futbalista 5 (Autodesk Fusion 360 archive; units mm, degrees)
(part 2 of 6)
sketch "Sketch25" plane through (0, 0, 31.7475) normal (0, 0, 1) x axis (-1, 0, 0)
  line L1 (-17.1956, -65) -> (-17.1956, -78.7443)
  curve K1 (-17.1956, -65) -> (-12.872, -63)
  line L2 (12.872, -63) -> (-12.872, -63)
  curve K2 (12.872, -63) -> (17.1956, -65)
  line L3 (17.1956, -78.7443) -> (17.1956, -65)
  line L4 (41.8394, -62.968) -> (43.3878, -65.6499)
  line L5 (43.3878, -57.718) -> (41.8394, -60.3999)
  line L6 (48.7086, -56.434) -> (45.6119, -56.434)
  line L7 (52.4811, -60.3999) -> (50.9327, -57.718)
  line L8 (75.4516, -15.25) -> (78.5484, -15.25)
  line L9 (71.6792, -11.2841) -> (73.2276, -13.9659)
  line L10 (73.2276, -6.0341) -> (71.6792, -8.7159)
  line L11 (78.5484, -4.75) -> (75.4516, -4.75)
  line L12 (64.8894, 17.6082) -> (76.7924, 24.4804)
  curve K3 (64.8894, 17.6082) -> (60.9956, 20.3525)
  line L13 (48.1236, 42.6475) -> (60.9956, 20.3525)
  curve K4 (48.1236, 42.6475) -> (47.6939, 47.3918)
  line L14 (59.5968, 54.264) -> (47.6939, 47.3918)
  line L15 (33.9041, 62.2984) -> (43.5123, 67.8457)
  line L16 (36.1352, 58.9119) -> (34.5869, 61.5938)
  line L17 (34.5869, 53.6619) -> (36.1352, 56.3438)
  line L18 (29.266, 52.3779) -> (32.3628, 52.3779)
  line L19 (25.4936, 56.3438) -> (27.042, 53.6619)
  line L20 (22.6078, 55.7765) -> (25.2248, 57.2874)
  line L21 (16.2, 55.5086) -> (21.6078, 55.5086)
  line L22 (16.2, 19.4846) -> (16.2, 55.5086)
  line L23 (13.8564, -18.3923) -> (22.8564, -2.8038)
  line L24 (-22.8564, -2.8038) -> (-13.8564, -18.3923)
  line L25 (-16.2, 55.5086) -> (-16.2, 19.4846)
  line L26 (-21.6078, 55.5086) -> (-16.2, 55.5086)
  line L27 (-25.2248, 57.2874) -> (-22.6078, 55.7765)
  line L28 (-27.042, 53.6619) -> (-25.4936, 56.3438)
  line L29 (-32.3628, 52.3779) -> (-29.266, 52.3779)
  line L30 (-36.1352, 56.3438) -> (-34.5869, 53.6619)
  line L31 (-34.5869, 61.5938) -> (-36.1352, 58.9119)
  line L32 (-43.5123, 67.8457) -> (-33.9041, 62.2984)
  line L33 (-47.6939, 47.3918) -> (-59.5968, 54.264)
  curve K5 (-47.6939, 47.3918) -> (-48.1236, 42.6475)
  line L34 (-60.9956, 20.3525) -> (-48.1236, 42.6475)
  curve K6 (-60.9956, 20.3525) -> (-64.8894, 17.6082)
  line L35 (-76.7924, 24.4804) -> (-64.8894, 17.6082)
  line L36 (-75.4516, -4.75) -> (-78.5484, -4.75)
  line L37 (-71.6792, -8.7159) -> (-73.2276, -6.0341)
  line L38 (-73.2276, -13.9659) -> (-71.6792, -11.2841)
  line L39 (-78.5484, -15.25) -> (-75.4516, -15.25)
  line L40 (-50.9327, -57.718) -> (-52.4811, -60.3999)
  line L41 (-45.6119, -56.434) -> (-48.7086, -56.434)
  line L42 (-41.8394, -60.3999) -> (-43.3878, -57.718)
  line L43 (-43.3878, -65.6499) -> (-41.8394, -62.968)
  line L44 (-13.8564, -18.3923) -> (-22.8564, -2.8038)
  line L45 (22.8564, -2.8038) -> (13.8564, -18.3923)
  line L46 (-9, 21.1962) -> (9, 21.1962)
  line L47 (-21.1244, -1.8038) -> (-12.1244, -17.3923)
  line L48 (9, 19.1962) -> (-9, 19.1962)
  line L49 (12.1244, -17.3923) -> (21.1244, -1.8038)
  line L50 (-20.5628, 59.4086) -> (20.5628, 59.4086)
  line L51 (-43.5858, 72.3915) -> (-21.5628, 59.6765)
  line L52 (21.5628, 59.6765) -> (43.5858, 72.3915)
  line L53 (-21.6078, 57.5086) -> (-43.5581, 70.1816)
  line L54 (21.6078, 57.5086) -> (-21.6078, 57.5086)
  line L55 (43.5581, 70.1816) -> (21.6078, 57.5086)
  line L56 (16.2, 55.5086) -> (-16.2, 55.5086)
  arc A1 centre (30.8144, 57.6279) radius 3.7 clockwise from (27.1259, 57.3359) to (27.1259, 57.9198)
  arc A2 centre (30.8144, 57.6279) radius 3.7 clockwise from (28.7173, 54.5795) to (27.1259, 57.3359)
  arc A3 centre (30.8144, 57.6279) radius 3.7 clockwise from (29.223, 54.2876) to (28.7173, 54.5795)
  arc A4 centre (30.8144, 57.6279) radius 3.7 clockwise from (32.4058, 54.2876) to (29.223, 54.2876)
  arc A5 centre (30.8144, 57.6279) radius 3.7 clockwise from (32.9115, 54.5795) to (32.4058, 54.2876)
  arc A6 centre (30.8144, 57.6279) radius 3.7 clockwise from (34.5029, 57.3359) to (32.9115, 54.5795)
  arc A7 centre (30.8144, 57.6279) radius 3.7 clockwise from (34.5029, 57.9198) to (34.5029, 57.3359)
  arc A8 centre (30.8144, 57.6279) radius 3.7 clockwise from (32.9115, 60.6762) to (34.5029, 57.9198)
  arc A9 centre (30.8144, 57.6279) radius 3.7 clockwise from (32.4058, 60.9682) to (32.9115, 60.6762)
  arc A10 centre (30.8144, 57.6279) radius 3.7 clockwise from (31.9266, 61.1568) to (32.4058, 60.9682)
  arc A11 centre (30.8144, 57.6279) radius 3.7 clockwise from (27.2022, 58.4291) to (31.9266, 61.1568)
  arc A12 centre (30.8144, 57.6279) radius 3.7 clockwise from (27.1259, 57.9198) to (27.2022, 58.4291)
  circle C1 centre (30.8144, 57.6279) radius 3.2
  arc A13 centre (-30.8144, 57.6279) radius 3.7 clockwise from (-34.5029, 57.3359) to (-34.5029, 57.9198)
  arc A14 centre (-30.8144, 57.6279) radius 3.7 clockwise from (-32.9115, 54.5795) to (-34.5029, 57.3359)
  arc A15 centre (-30.8144, 57.6279) radius 3.7 clockwise from (-32.4058, 54.2876) to (-32.9115, 54.5795)
  arc A16 centre (-30.8144, 57.6279) radius 3.7 clockwise from (-29.223, 54.2876) to (-32.4058, 54.2876)
  arc A17 centre (-30.8144, 57.6279) radius 3.7 clockwise from (-28.7173, 54.5795) to (-29.223, 54.2876)
  arc A18 centre (-30.8144, 57.6279) radius 3.7 clockwise from (-27.1259, 57.3359) to (-28.7173, 54.5795)
  arc A19 centre (-30.8144, 57.6279) radius 3.7 clockwise from (-27.1259, 57.9198) to (-27.1259, 57.3359)
  arc A20 centre (-30.8144, 57.6279) radius 3.7 clockwise from (-27.2022, 58.4291) to (-27.1259, 57.9198)
  arc A21 centre (-30.8144, 57.6279) radius 3.7 clockwise from (-31.9266, 61.1568) to (-27.2022, 58.4291)
  arc A22 centre (-30.8144, 57.6279) radius 3.7 clockwise from (-32.4058, 60.9682) to (-31.9266, 61.1568)
  arc A23 centre (-30.8144, 57.6279) radius 3.7 clockwise from (-32.9115, 60.6762) to (-32.4058, 60.9682)
  arc A24 centre (-30.8144, 57.6279) radius 3.7 clockwise from (-34.5029, 57.9198) to (-32.9115, 60.6762)
  circle C2 centre (-30.8144, 57.6279) radius 3.2
  arc A25 centre (-77, -10) radius 3.7 clockwise from (-79.6046, -12.6279) to (-80.1895, -8.1246)
  arc A26 centre (-77, -10) radius 3.7 clockwise from (-79.0971, -13.0483) to (-79.6046, -12.6279)
  arc A27 centre (-77, -10) radius 3.7 clockwise from (-78.5914, -13.3403) to (-79.0971, -13.0483)
  arc A28 centre (-77, -10) radius 3.7 clockwise from (-75.4086, -13.3403) to (-78.5914, -13.3403)
  arc A29 centre (-77, -10) radius 3.7 clockwise from (-74.9029, -13.0483) to (-75.4086, -13.3403)
  arc A30 centre (-77, -10) radius 3.7 clockwise from (-73.3115, -10.2919) to (-74.9029, -13.0483)
  arc A31 centre (-77, -10) radius 3.7 clockwise from (-73.3115, -9.7081) to (-73.3115, -10.2919)
  arc A32 centre (-77, -10) radius 3.7 clockwise from (-74.9029, -6.9517) to (-73.3115, -9.7081)
  arc A33 centre (-77, -10) radius 3.7 clockwise from (-75.4086, -6.6597) to (-74.9029, -6.9517)
  arc A34 centre (-77, -10) radius 3.7 clockwise from (-78.5914, -6.6597) to (-75.4086, -6.6597)
  arc A35 centre (-77, -10) radius 3.7 clockwise from (-79.0971, -6.9517) to (-78.5914, -6.6597)
  arc A36 centre (-77, -10) radius 3.7 clockwise from (-80.1895, -8.1246) to (-79.0971, -6.9517)
  circle C3 centre (-77, -10) radius 3.2
  arc A37 centre (-47.1603, -61.684) radius 3.7 clockwise from (-50.8487, -61.9759) to (-50.8487, -61.392)
  arc A38 centre (-47.1603, -61.684) radius 3.7 clockwise from (-50.7384, -62.6257) to (-50.8487, -61.9759)
  arc A39 centre (-47.1603, -61.684) radius 3.7 clockwise from (-47.1308, -65.3838) to (-50.7384, -62.6257)
  arc A40 centre (-47.1603, -61.684) radius 3.7 clockwise from (-45.5689, -65.0242) to (-47.1308, -65.3838)
  arc A41 centre (-47.1603, -61.684) radius 3.7 clockwise from (-45.0632, -64.7323) to (-45.5689, -65.0242)
  arc A42 centre (-47.1603, -61.684) radius 3.7 clockwise from (-43.4718, -61.9759) to (-45.0632, -64.7323)
  arc A43 centre (-47.1603, -61.684) radius 3.7 clockwise from (-43.4718, -61.392) to (-43.4718, -61.9759)
  arc A44 centre (-47.1603, -61.684) radius 3.7 clockwise from (-45.0632, -58.6356) to (-43.4718, -61.392)
  arc A45 centre (-47.1603, -61.684) radius 3.7 clockwise from (-45.5689, -58.3437) to (-45.0632, -58.6356)
  arc A46 centre (-47.1603, -61.684) radius 3.7 clockwise from (-48.7517, -58.3437) to (-45.5689, -58.3437)
  arc A47 centre (-47.1603, -61.684) radius 3.7 clockwise from (-49.2573, -58.6356) to (-48.7517, -58.3437)
  arc A48 centre (-47.1603, -61.684) radius 3.7 clockwise from (-50.8487, -61.392) to (-49.2573, -58.6356)
  circle C4 centre (-47.1603, -61.684) radius 3.2
  arc A49 centre (47.1603, -61.684) radius 3.7 clockwise from (43.4718, -61.9759) to (43.4718, -61.392)
  arc A50 centre (47.1603, -61.684) radius 3.7 clockwise from (45.0632, -64.7323) to (43.4718, -61.9759)
  arc A51 centre (47.1603, -61.684) radius 3.7 clockwise from (45.5689, -65.0242) to (45.0632, -64.7323)
  arc A52 centre (47.1603, -61.684) radius 3.7 clockwise from (47.1308, -65.3838) to (45.5689, -65.0242)
  arc A53 centre (47.1603, -61.684) radius 3.7 clockwise from (50.7384, -62.6257) to (47.1308, -65.3838)
  arc A54 centre (47.1603, -61.684) radius 3.7 clockwise from (50.8487, -61.9759) to (50.7384, -62.6257)
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  point P195 (-16.2, 55.5086)
  point P318 (-16.2, 55.5086)
  point P185 (16.2, 55.5086)
  point P319 (16.2, 55.5086)
  coincident P195 P318
  coincident P185 P319
extrude "Extrude41" new body of existing geometry blind 25
extrude "Extrude39" add sketch "Sketch25" against normal blind 3
circular_pattern "C-Pattern8" TotalAngle 360
combine "Combine20"
extrude "Extrude40" cut sketch "Sketch25" against normal blind 20 and along normal blind 10
extrude "Extrude42" cut sketch "Sketch25" along normal blind 9.003
offset_faces "OffsetFaces11" distance 0.003
sketch "Sketch26" plane through (0, 0, 31.7505) normal (0, 0, 1) x axis (-1, 0, 0)
  line L1 (13.8564, -18.3923) -> (22.8564, -2.8038)
  line L2 (-22.8564, -2.8038) -> (-13.8564, -18.3923)
  line L3 (9, 21.1962) -> (-9, 21.1962)
  line L4 (-21.6078, 55.5086) -> (21.6078, 55.5086)
  line L5 (-27.2022, 58.4291) -> (-22.6078, 55.7765)
  line L6 (-43.5123, 67.8457) -> (-31.9266, 61.1568)
  line L7 (-50.9495, 41.7529) -> (-63.8435, 49.1973)
  curve K1 (-50.9495, 41.7529) -> (-61.6338, 23.2471)
  line L8 (-74.5278, 30.6914) -> (-61.6338, 23.2471)
  line L9 (-10.6844, -65) -> (-10.6844, -79.8887)
  curve K2 (-10.6844, -65) -> (10.6844, -65)
  line L10 (10.6844, -79.8887) -> (10.6844, -65)
  line L11 (61.6338, 23.2471) -> (74.5278, 30.6914)
  curve K3 (61.6338, 23.2471) -> (50.9495, 41.7529)
  line L12 (63.8435, 49.1973) -> (50.9495, 41.7529)
  line L13 (31.9266, 61.1568) -> (43.5123, 67.8457)
  line L14 (22.6078, 55.7765) -> (27.2022, 58.4291)
  circle C1 centre (-47.1603, -61.684) radius 3.2
  circle C2 centre (-77, -10) radius 3.2
  circle C3 centre (47.1603, -61.684) radius 3.2
  arc A1 centre (9, 5.1962) radius 16 clockwise from (9, 21.1962) to (22.8564, -2.8038)
  arc A2 centre (0, -10.3923) radius 16 clockwise from (13.8564, -18.3923) to (-13.8564, -18.3923)
  arc A3 centre (-9, 5.1962) radius 16 clockwise from (-22.8564, -2.8038) to (-9, 21.1962)
  circle C4 centre (-29, -52.2) radius 1.35
  circle C5 centre (29, -3.2) radius 1.35
  circle C6 centre (29, -52.2) radius 1.35
  circle C7 centre (-29, -3.2) radius 1.35
  arc A4 centre (-21.6078, 57.5086) radius 2 clockwise from (-21.6078, 55.5086) to (-22.6078, 55.7765)
  arc A5 centre (-30.8144, 57.6279) radius 3.7 clockwise from (-31.9266, 61.1568) to (-27.2022, 58.4291)
  arc A6 centre (0, 0) radius 80.6 clockwise from (-63.8435, 49.1973) to (-43.5123, 67.8457)
  arc A7 centre (0, 0) radius 80.6 clockwise from (-80.1895, -8.1246) to (-74.5278, 30.6914)
  arc A8 centre (-77, -10) radius 3.7 clockwise from (-79.6046, -12.6279) to (-80.1895, -8.1246)
  arc A9 centre (0, 0) radius 80.6 clockwise from (-50.7384, -62.6257) to (-79.6046, -12.6279)
  arc A10 centre (-47.1603, -61.684) radius 3.7 clockwise from (-47.1308, -65.3838) to (-50.7384, -62.6257)
  arc A11 centre (0, 0) radius 80.6 clockwise from (-10.6844, -79.8887) to (-47.1308, -65.3838)
  arc A12 centre (0, 0) radius 80.6 clockwise from (47.1308, -65.3838) to (10.6844, -79.8887)
  arc A13 centre (47.1603, -61.684) radius 3.7 clockwise from (50.7384, -62.6257) to (47.1308, -65.3838)
  arc A14 centre (0, 0) radius 80.6 clockwise from (79.6046, -12.6279) to (50.7384, -62.6257)
  arc A15 centre (77, -10) radius 3.7 clockwise from (80.1895, -8.1246) to (79.6046, -12.6279)
  arc A16 centre (0, 0) radius 80.6 clockwise from (74.5278, 30.6914) to (80.1895, -8.1246)
  arc A17 centre (0, 0) radius 80.6 clockwise from (43.5123, 67.8457) to (63.8435, 49.1973)
  arc A18 centre (30.8144, 57.6279) radius 3.7 clockwise from (27.2022, 58.4291) to (31.9266, 61.1568)
  arc A19 centre (21.6078, 57.5086) radius 2 clockwise from (22.6078, 55.7765) to (21.6078, 55.5086)
  circle C8 centre (30.8144, 57.6279) radius 3.2
  circle C9 centre (-30.8144, 57.6279) radius 3.2
  circle C10 centre (77, -10) radius 3.2
  circle C11 centre (0, 0) radius 80.6
  point P35 (-10.6844, -79.8887)
  concentric A6 C11
  coincident P35 C11
extrude "Extrude43" cut sketch "Sketch26" profile of L7 K1 L8 L9 K2 L10 L11 K3 L12 C11 along normal blind 59
sketch "Sketch27" plane through (0, 0, 26.75) normal (0, 0, -1) x axis (1, 0, 0)
  line L1 (12.1244, -17.3923) -> (21.1244, -1.8038)
  line L2 (-21.1244, -1.8038) -> (-12.1244, -17.3923)
  line L3 (9, 19.1962) -> (-9, 19.1962)
  line L4 (-29.266, 60.8779) -> (-32.3628, 60.8779)
  line L5 (-27.2256, 57.9119) -> (-28.774, 60.5938)
  line L6 (-28.774, 54.6619) -> (-27.2256, 57.3438)
  line L7 (-32.3628, 54.3779) -> (-29.266, 54.3779)
  line L8 (-34.4032, 57.3438) -> (-32.8548, 54.6619)
  line L9 (-32.8548, 60.5938) -> (-34.4032, 57.9119)
  line L10 (-78.5484, -13.25) -> (-75.4516, -13.25)
  line L11 (-80.5888, -10.2841) -> (-79.0404, -12.9659)
  line L12 (-79.0404, -7.0341) -> (-80.5888, -9.7159)
  line L13 (-75.4516, -6.75) -> (-78.5484, -6.75)
  line L14 (-73.4112, -9.7159) -> (-74.9596, -7.0341)
  line L15 (-74.9596, -12.9659) -> (-73.4112, -10.2841)
  line L16 (50.749, -61.3999) -> (49.2006, -58.718)
  line L17 (49.2006, -64.6499) -> (50.749, -61.968)
  line L18 (45.6119, -64.934) -> (48.7086, -64.934)
  line L19 (43.5715, -61.968) -> (45.1199, -64.6499)
  line L20 (45.1199, -58.718) -> (43.5715, -61.3999)
  line L21 (48.7086, -58.434) -> (45.6119, -58.434)
  line L22 (32.3628, 60.8779) -> (29.266, 60.8779)
  line L23 (34.4032, 57.9119) -> (32.8548, 60.5938)
  line L24 (32.8548, 54.6619) -> (34.4032, 57.3438)
  line L25 (29.266, 54.3779) -> (32.3628, 54.3779)
  line L26 (27.2256, 57.3438) -> (28.774, 54.6619)
  line L27 (28.774, 60.5938) -> (27.2256, 57.9119)
  line L28 (75.4516, -13.25) -> (78.5484, -13.25)
  line L29 (73.4112, -10.2841) -> (74.9596, -12.9659)
  line L30 (74.9596, -7.0341) -> (73.4112, -9.7159)
  line L31 (78.5484, -6.75) -> (75.4516, -6.75)
  line L32 (80.5888, -9.7159) -> (79.0404, -7.0341)
  line L33 (79.0404, -12.9659) -> (80.5888, -10.2841)
  line L34 (-49.2006, -58.718) -> (-50.749, -61.3999)
  line L35 (-45.6119, -58.434) -> (-48.7086, -58.434)
  line L36 (-43.5715, -61.3999) -> (-45.1199, -58.718)
  line L37 (-45.1199, -64.6499) -> (-43.5715, -61.968)
  line L38 (-48.7086, -64.934) -> (-45.6119, -64.934)
  line L39 (-50.749, -61.968) -> (-49.2006, -64.6499)
  line L40 (-21.6078, 57.5086) -> (21.6078, 57.5086)
  line L41 (-42.5123, 69.5778) -> (-21.6078, 57.5086)
  line L42 (-47.9747, 46.9054) -> (-61.7512, 54.8593)
  line L43 (-64.6086, 18.0946) -> (-47.9747, 46.9054)
  line L44 (-78.3852, 26.0485) -> (-64.6086, 18.0946)
  line L45 (-16.6339, -65) -> (-16.6339, -80.9078)
  line L46 (16.6339, -65) -> (-16.6339, -65)
  line L47 (16.6339, -80.9078) -> (16.6339, -65)
  line L48 (64.6086, 18.0946) -> (78.3852, 26.0485)
  line L49 (47.9747, 46.9054) -> (64.6086, 18.0946)
  line L50 (61.7512, 54.8593) -> (47.9747, 46.9054)
  line L51 (21.6078, 57.5086) -> (42.5123, 69.5778)
  line L52 (3, 0) -> (0, 0)
  line L53 (3, -24.0671) -> (3, -5.1962)
  line L54 (-3, -24.0671) -> (-3, -5.1962)
  line L55 (19.3427, 14.6316) -> (3, 5.1962)
  line L56 (22.3427, 9.4355) -> (6, 0)
  line L57 (-22.3427, 9.4355) -> (-6, 0)
  line L58 (-19.3427, 14.6316) -> (-3, 5.1962)
  arc A1 centre (9, 5.1962) radius 14 clockwise from (9, 19.1962) to (21.1244, -1.8038)
  arc A2 centre (0, -10.3923) radius 14 clockwise from (12.1244, -17.3923) to (-12.1244, -17.3923)
  arc A3 centre (-9, 5.1962) radius 14 clockwise from (-21.1244, -1.8038) to (-9, 19.1962)
  arc A4 centre (-30.8144, 57.6279) radius 3.6 clockwise from (-32.8548, 60.5938) to (-32.3628, 60.8779)
  arc A5 centre (-30.8144, 57.6279) radius 3.6 clockwise from (-29.266, 60.8779) to (-28.774, 60.5938)
  arc A6 centre (-30.8144, 57.6279) radius 3.6 clockwise from (-27.2256, 57.9119) to (-27.2256, 57.3438)
  arc A7 centre (-30.8144, 57.6279) radius 3.6 clockwise from (-28.774, 54.6619) to (-29.266, 54.3779)
  arc A8 centre (-30.8144, 57.6279) radius 3.6 clockwise from (-32.3628, 54.3779) to (-32.8548, 54.6619)
  arc A9 centre (-30.8144, 57.6279) radius 3.6 clockwise from (-34.4032, 57.3438) to (-34.4032, 57.9119)
  arc A10 centre (-77, -10) radius 3.6 clockwise from (-74.9596, -12.9659) to (-75.4516, -13.25)
  arc A11 centre (-77, -10) radius 3.6 clockwise from (-78.5484, -13.25) to (-79.0404, -12.9659)
  arc A12 centre (-77, -10) radius 3.6 clockwise from (-80.5888, -10.2841) to (-80.5888, -9.7159)
  arc A13 centre (-77, -10) radius 3.6 clockwise from (-79.0404, -7.0341) to (-78.5484, -6.75)
  arc A14 centre (-77, -10) radius 3.6 clockwise from (-75.4516, -6.75) to (-74.9596, -7.0341)
  arc A15 centre (-77, -10) radius 3.6 clockwise from (-73.4112, -9.7159) to (-73.4112, -10.2841)
  circle C1 centre (-29, -52.2) radius 1.35
  arc A16 centre (47.1603, -61.684) radius 3.6 clockwise from (48.7086, -58.434) to (49.2006, -58.718)
  arc A17 centre (47.1603, -61.684) radius 3.6 clockwise from (50.749, -61.3999) to (50.749, -61.968)
  arc A18 centre (47.1603, -61.684) radius 3.6 clockwise from (49.2006, -64.6499) to (48.7086, -64.934)
  arc A19 centre (47.1603, -61.684) radius 3.6 clockwise from (45.6119, -64.934) to (45.1199, -64.6499)
  arc A20 centre (47.1603, -61.684) radius 3.6 clockwise from (43.5715, -61.968) to (43.5715, -61.3999)
  arc A21 centre (47.1603, -61.684) radius 3.6 clockwise from (45.1199, -58.718) to (45.6119, -58.434)
  circle C2 centre (29, -52.2) radius 1.35
  arc A22 centre (30.8144, 57.6279) radius 3.6 clockwise from (28.774, 60.5938) to (29.266, 60.8779)
  arc A23 centre (30.8144, 57.6279) radius 3.6 clockwise from (32.3628, 60.8779) to (32.8548, 60.5938)
  arc A24 centre (30.8144, 57.6279) radius 3.6 clockwise from (34.4032, 57.9119) to (34.4032, 57.3438)
  arc A25 centre (30.8144, 57.6279) radius 3.6 clockwise from (32.8548, 54.6619) to (32.3628, 54.3779)
  arc A26 centre (30.8144, 57.6279) radius 3.6 clockwise from (29.266, 54.3779) to (28.774, 54.6619)
  arc A27 centre (30.8144, 57.6279) radius 3.6 clockwise from (27.2256, 57.3438) to (27.2256, 57.9119)
  arc A28 centre (77, -10) radius 3.6 clockwise from (79.0404, -12.9659) to (78.5484, -13.25)
  arc A29 centre (77, -10) radius 3.6 clockwise from (75.4516, -13.25) to (74.9596, -12.9659)
  arc A30 centre (77, -10) radius 3.6 clockwise from (73.4112, -10.2841) to (73.4112, -9.7159)
  arc A31 centre (77, -10) radius 3.6 clockwise from (74.9596, -7.0341) to (75.4516, -6.75)
  arc A32 centre (77, -10) radius 3.6 clockwise from (78.5484, -6.75) to (79.0404, -7.0341)
  arc A33 centre (77, -10) radius 3.6 clockwise from (80.5888, -9.7159) to (80.5888, -10.2841)
  circle C3 centre (-29, -3.2) radius 1.35
  circle C4 centre (29, -3.2) radius 1.35
  arc A34 centre (-47.1603, -61.684) radius 3.6 clockwise from (-50.749, -61.968) to (-50.749, -61.3999)
  arc A35 centre (-47.1603, -61.684) radius 3.6 clockwise from (-49.2006, -58.718) to (-48.7086, -58.434)
  arc A36 centre (-47.1603, -61.684) radius 3.6 clockwise from (-45.6119, -58.434) to (-45.1199, -58.718)
  arc A37 centre (-47.1603, -61.684) radius 3.6 clockwise from (-43.5715, -61.3999) to (-43.5715, -61.968)
  arc A38 centre (-47.1603, -61.684) radius 3.6 clockwise from (-45.1199, -64.6499) to (-45.6119, -64.934)
  arc A39 centre (-47.1603, -61.684) radius 3.6 clockwise from (-48.7086, -64.934) to (-49.2006, -64.6499)
  arc A40 centre (-43.5123, 67.8457) radius 2 clockwise from (-44.592, 69.5292) to (-42.5123, 69.5778)
  arc A41 centre (0, 0) radius 82.6 clockwise from (-61.7512, 54.8593) to (-44.592, 69.5292)
  arc A42 centre (0, 0) radius 82.6 clockwise from (-16.6339, -80.9078) to (-78.3852, 26.0485)
  arc A43 centre (0, 0) radius 82.6 clockwise from (78.3852, 26.0485) to (16.6339, -80.9078)
  arc A44 centre (0, 0) radius 82.6 clockwise from (44.592, 69.5292) to (61.7512, 54.8593)
  arc A45 centre (43.5123, 67.8457) radius 2 clockwise from (42.5123, 69.5778) to (44.592, 69.5292)
  arc A46 centre (9, -5.1962) radius 6 clockwise from (3, -5.1962) to (6, 0)
  arc A47 centre (-9, -5.1962) radius 6 clockwise from (-6, 0) to (-3, -5.1962)
  arc A48 centre (0, 10.3923) radius 6 clockwise from (3, 5.1962) to (-3, 5.1962)
  point P1 (0, 0)
  point P114 (0, 0)
  point P116 (3, -24.0671)
  point P117 (-3, -24.0671)
  point P115 (3, 0)
  coincident P1 P114
  coincident A2 P116
  perpendicular L52 L53
  coincident A2 P117
  perpendicular L52 L54
  coincident P115 L53
  tangent L56 A46
  tangent L53 A46
  tangent L54 A47
  tangent L57 A47
  equal A46 A47
  tangent L58 A48
  tangent L55 A48
  equal A46 A48
  dimension "d232" radius A46 = 6
extrude "Extrude44" add sketch "Sketch27" profile of A1 A2 A3 L53 L54 L55 L56 L57 L58 A46 A47 A48 against normal blind 3
position "Position24"
sketch "Sketch28" plane through (0, 0, 31.7505) normal (0, 0, 1) x axis (-1, 0, 0)
  line L1 (13.8564, -18.3923) -> (22.8564, -2.8038)
  line L2 (-22.8564, -2.8038) -> (-13.8564, -18.3923)
  line L3 (9, 21.1962) -> (-9, 21.1962)
  line L4 (-21.6078, 55.5086) -> (21.6078, 55.5086)
  line L5 (-27.2022, 58.4291) -> (-22.6078, 55.7765)
  line L6 (-43.5123, 67.8457) -> (-31.9266, 61.1568)
  line L7 (31.9266, 61.1568) -> (43.5123, 67.8457)
  line L8 (22.6078, 55.7765) -> (27.2022, 58.4291)
  line L9 (-14, 32.5) -> (-14, 39.5)
  line L10 (14, 32.5) -> (-14, 32.5)
  line L11 (14, 39.5) -> (14, 32.5)
  line L12 (-14, 39.5) -> (14, 39.5)
  line L13 (14, 20.3948) -> (14, 32.5)
  line L14 (-14, 20.3948) -> (-14, 32.5)
  line L15 (-20.5628, 59.4086) -> (20.5628, 59.4086)
  line L16 (-43.5858, 72.3915) -> (-21.5628, 59.6765)
  line L17 (21.5628, 59.6765) -> (43.5858, 72.3915)
  line L18 (-21.6078, 57.5086) -> (-43.5581, 70.1816)
  line L19 (21.6078, 57.5086) -> (-21.6078, 57.5086)
  line L20 (43.5581, 70.1816) -> (21.6078, 57.5086)
  line L21 (-14, 57.5086) -> (-14, 39.5)
  line L22 (14, 57.5086) -> (14, 39.5)
  line L23 (-21.6078, 57.5086) -> (-21.6078, 39.5)
  line L24 (-21.6078, 15.0472) -> (-21.6078, 39.5)
  line L25 (21.6078, 15.0472) -> (21.6078, 39.5)
  line L26 (21.6078, 57.5086) -> (21.6078, 39.5)
  line L27 (25, 5.1961) -> (-25, 5.1962)
  line L28 (25, 59.4671) -> (25, 5.1961)
  line L29 (-25, 59.4671) -> (-25, 5.1962)
  line L30 (-2, 53.9086) -> (-2, 22.7962)
  line L31 (-5.2, 22.7962) -> (-5.2, 53.9086)
  line L32 (-3.6, 55.5086) -> (-3.6, 21.1962)
  line L33 (5.2, 53.9086) -> (5.2, 22.7962)
  line L34 (2, 22.7962) -> (2, 53.9086)
  line L35 (3.6, 55.5086) -> (3.6, 21.1962)
  line L36 (21.6078, 21.1962) -> (0, 21.1962)
  line L37 (-21.6078, 21.1962) -> (0, 21.1962)
  line L38 (25, 61.661) -> (25, 59.4671)
  line L39 (-25, 61.661) -> (-25, 59.4671)
  circle C1 centre (-47.1603, -61.684) radius 3.2
  circle C2 centre (-77, -10) radius 3.2
  circle C3 centre (47.1603, -61.684) radius 3.2
  arc A1 centre (9, 5.1962) radius 16 clockwise from (9, 21.1962) to (22.8564, -2.8038)
  arc A2 centre (0, -10.3923) radius 16 clockwise from (13.8564, -18.3923) to (-13.8564, -18.3923)
  arc A3 centre (-9, 5.1962) radius 16 clockwise from (-22.8564, -2.8038) to (-9, 21.1962)
  circle C4 centre (-29, -52.2) radius 1.35
  circle C5 centre (29, -3.2) radius 1.35
  circle C6 centre (29, -52.2) radius 1.35
  circle C7 centre (-29, -3.2) radius 1.35
  arc A4 centre (-21.6078, 57.5086) radius 2 clockwise from (-21.6078, 55.5086) to (-22.6078, 55.7765)
  arc A5 centre (-30.8144, 57.6279) radius 3.7 clockwise from (-31.9266, 61.1568) to (-27.2022, 58.4291)
  arc A6 centre (0, 0) radius 80.6 clockwise from (-80.1895, -8.1246) to (-43.5123, 67.8457)
  arc A7 centre (-77, -10) radius 3.7 clockwise from (-79.6046, -12.6279) to (-80.1895, -8.1246)
  arc A8 centre (0, 0) radius 80.6 clockwise from (-50.7384, -62.6257) to (-79.6046, -12.6279)
  arc A9 centre (-47.1603, -61.684) radius 3.7 clockwise from (-47.1308, -65.3838) to (-50.7384, -62.6257)
  arc A10 centre (0, 0) radius 80.6 clockwise from (47.1308, -65.3838) to (-47.1308, -65.3838)
  arc A11 centre (47.1603, -61.684) radius 3.7 clockwise from (50.7384, -62.6257) to (47.1308, -65.3838)
  arc A12 centre (0, 0) radius 80.6 clockwise from (79.6046, -12.6279) to (50.7384, -62.6257)
  arc A13 centre (77, -10) radius 3.7 clockwise from (80.1895, -8.1246) to (79.6046, -12.6279)
  arc A14 centre (0, 0) radius 80.6 clockwise from (43.5123, 67.8457) to (80.1895, -8.1246)
  arc A15 centre (30.8144, 57.6279) radius 3.7 clockwise from (27.2022, 58.4291) to (31.9266, 61.1568)
  arc A16 centre (21.6078, 57.5086) radius 2 clockwise from (22.6078, 55.7765) to (21.6078, 55.5086)
  circle C8 centre (30.8144, 57.6279) radius 3.2
  circle C9 centre (-30.8144, 57.6279) radius 3.2
  circle C10 centre (77, -10) radius 3.2
  circle C11 centre (3.6, 36) radius 1.6
  circle C12 centre (-3.6, 36) radius 1.6
  arc A17 centre (-20.5628, 61.4086) radius 2 clockwise from (-20.5628, 59.4086) to (-21.5628, 59.6765)
  arc A18 centre (0, 0) radius 84.5 clockwise from (43.5858, 72.3915) to (-43.5858, 72.3915)
  arc A19 centre (20.5628, 61.4086) radius 2 clockwise from (21.5628, 59.6765) to (20.5628, 59.4086)
  arc A20 centre (0, 0) radius 82.6 clockwise from (43.5581, 70.1816) to (-43.5581, 70.1816)
  arc A21 centre (-3.6, 53.9086) radius 1.6 clockwise from (-5.2, 53.9086) to (-2, 53.9086)
  arc A22 centre (-3.6, 22.7962) radius 1.6 clockwise from (-2, 22.7962) to (-5.2, 22.7962)
  arc A23 centre (3.6, 53.9086) radius 1.6 clockwise from (2, 53.9086) to (5.2, 53.9086)
  arc A24 centre (3.6, 22.7962) radius 1.6 clockwise from (5.2, 22.7962) to (2, 22.7962)
  point P46 (14, 32.5)
  point P48 (14, 32.5)
  point P49 (14, 20.3948)
  point P45 (-14, 32.5)
  point P50 (-14, 32.5)
  point P51 (-14, 20.3948)
  point P44 (-14, 39.5)
  point P65 (-14, 39.5)
  point P66 (-14, 57.5086)
  point P47 (14, 39.5)
  point P67 (14, 39.5)
  point P63 (-21.6078, 57.5086)
  point P70 (-21.6078, 57.5086)
  point P71 (-21.6078, 15.0472)
  point P75 (-25, 5.1962)
  point P76 (25, 5.1961)
  point P77 (25, 59.4671)
  point P78 (-25, 59.4671)
  point P85 (-3.6, 21.1962)
  point P86 (-3.6, 55.5086)
  point P93 (3.6, 21.1962)
  point P94 (3.6, 55.5086)
  point P95 (0, 21.1962)
  point P96 (21.6078, 21.1962)
  point P97 (-21.6078, 21.1962)
  point P98 (25, 61.661)
  point P99 (-25, 61.661)
  coincident P46 P48
  coincident A1 P49
  perpendicular L10 L13
  coincident P45 P50
  coincident A3 P51
  perpendicular L10 L14
  coincident P44 P65
  coincident L19 P66
  perpendicular L19 L21
  coincident P47 P67
  perpendicular L4 L22
  coincident P63 P70
  perpendicular L19 L23
  coincident A3 P71
  coincident A3 P75
  coincident A1 P76
  coincident L20 P77
  perpendicular L27 L28
  coincident L18 P78
  perpendicular L27 L29
  tangent L30 A21
  tangent A21 L31
  parallel L30 L31
  tangent L31 A22
  tangent L30 A22
  midpoint A22 P85
  midpoint A21 P86
  perpendicular L4 L32
  coincident L3 P85
  tangent L33 A23
  tangent A23 L34
  parallel L33 L34
  tangent L34 A24
  tangent L33 A24
  midpoint A24 P93
  midpoint A23 P94
  coincident L4 P94
  perpendicular L4 L35
  coincident L3 P93
  midpoint L3 P95
  coincident L25 P96
  perpendicular L25 L36
  coincident L24 P97
  perpendicular L24 L37
  coincident L17 P98
  parallel L28 L38
  coincident L16 P99
  parallel L29 L39
extrude "Extrude45" add sketch "Sketch28" profile of A1 A3 L4 A4 L5 L8 A16 L13 L14 L15 A17 L16 L17 A19 L18 L19 L20 L21 L22 L23 L24 L25 L26 L28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 along normal blind 8
extrude "Extrude46" cut sketch "Sketch28" profile of L3 L4 C11 C12 L9 L10 L11 L12 L13 L14 L21 L22 L23 L24 L25 L26 L30 A21 L31 A22 L33 A23 L34 A24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 against normal blind 5.0005
extrude "Extrude47" add sketch "Sketch28" profile of A1 A3 L3 L4 A4 L5 L8 A16 L9 L10 L11 L12 L13 L14 L15 A17 L16 L17 A19 L18 L19 L20 L21 L22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 along normal blind 8.9995 and along normal blind 8
extrude "Extrude48" add of existing geometry blind 26.5 second side blind -20
extrude "Extrude49" cut of existing geometry blind -4
extrude "Extrude50" add of existing geometry blind 1.5
extrude "Extrude51" cut of existing geometry blind -2.9995
sketch "Sketch30" plane through (0, 0, -23.25) normal (0, 0, 1) x axis (-1, 0, 0)
  line L1 (11.2, 24.5) -> (-11.2, 24.5)
  line L2 (11.2, 61.4086) -> (11.2, 24.5)
  line L3 (-11.2, 61.4086) -> (11.2, 61.4086)
  line L4 (-11.2, 24.5) -> (-11.2, 61.4086)
  line L5 (21.0719, 59.5086) -> (-21.0719, 59.5086)
  line L6 (11.2, 59.5086) -> (21.0719, 59.5086)
  line L7 (-11.2, 59.5086) -> (11.2, 59.5086)
  line L8 (-21.0719, 59.5086) -> (-11.2, 59.5086)
  line L9 (14.2, 59.5086) -> (-14.2, 59.5086)
  line L10 (-14.2, 59.5086) -> (14.2, 59.5086)
  line L11 (-21.0719, 59.5086) -> (-42.5581, 71.9136)
  line L12 (-42.5581, 71.9136) -> (-21.0719, 59.5086)
  line L13 (21.0719, 59.5086) -> (42.5581, 71.9136)
  line L14 (42.5581, 71.9136) -> (21.0719, 59.5086)
  line L15 (30.8285, 65.6035) -> (21.4288, 60.1765)
  line L16 (30.0785, 66.9025) -> (30.8285, 65.6035)
  line L17 (20.5628, 61.4086) -> (30.0785, 66.9025)
  line L18 (11.2, 61.4086) -> (20.5628, 61.4086)
  line L19 (11.2, 59.9086) -> (11.2, 61.4086)
  line L20 (20.4288, 59.9086) -> (11.2, 59.9086)
  line L21 (-11.2, 59.9086) -> (-20.4288, 59.9086)
  line L22 (-11.2, 61.4086) -> (-11.2, 59.9086)
  line L23 (-20.5628, 61.4086) -> (-11.2, 61.4086)
  line L24 (-30.0785, 66.9025) -> (-20.5628, 61.4086)
  line L25 (-30.8285, 65.6035) -> (-30.0785, 66.9025)
  line L26 (-21.4288, 60.1765) -> (-30.8285, 65.6035)
  line L27 (-31.0285, 65.257) -> (-30.8285, 65.6035)
  line L28 (31.0285, 65.257) -> (30.8285, 65.6035)
  line L29 (-11.2, 59.9086) -> (11.2, 59.9086)
  circle C1 centre (-6, 30.7) radius 1.7
  circle C2 centre (6, 44.2) radius 1.7
  arc A1 centre (20.4288, 61.9086) radius 2 clockwise from (21.4288, 60.1765) to (20.4288, 59.9086)
  arc A2 centre (-20.4288, 61.9086) radius 2 clockwise from (-20.4288, 59.9086) to (-21.4288, 60.1765)
  point P33 (-30.8285, 65.6035)
  point P34 (-30.8285, 65.6035)
  point P35 (-31.0285, 65.257)
  point P21 (30.8285, 65.6035)
  point P36 (30.8285, 65.6035)
  point P37 (31.0285, 65.257)
  point P25 (11.2, 59.9086)
  point P38 (11.2, 59.9086)
  point P29 (-11.2, 59.9086)
  point P39 (-11.2, 59.9086)
  coincident P33 P34
  coincident L12 P35
  perpendicular L12 L27
  coincident P21 P36
  coincident L13 P37
  perpendicular L13 L28
  coincident P25 P38
  coincident P29 P39
extrude "Extrude55" new body sketch "Sketch30" profile of L2 L3 L4 L5 L6 L7 L8 L9 L10 L11 L12 L13 L14 A1 L15 L16 L17 L18 L19 L20 A2 L21 L22 L23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 along normal blind 27.5 and along normal blind 7
extrude "Extrude56" new body of existing geometry blind 2.6
extrude "Extrude57" add of existing geometry blind 0.309
offset_faces "OffsetFaces12" distance -0.2
draft "Draft1" Angle1 45 Angle2 0
draft "Draft2" Angle1 45 Angle2 0
sketch "Sketch31" plane through (0, 0, 0) normal (0, 1, 0) x axis (1, 0, 0)
  line L1 (-73.8, -31.7505) -> (-80.2, -31.7505)
  line L2 (34.0144, -31.7505) -> (27.6144, -31.7505)
  line L3 (-27.6144, -31.7505) -> (-34.0144, -31.7505)
  line L4 (27.65, -31.7505) -> (30.35, -31.7505)
  line L5 (-30.35, -31.7505) -> (-27.65, -31.7505)
  line L6 (-30.35, -31.7505) -> (-27.65, -31.7505)
  line L7 (27.65, -31.7505) -> (30.35, -31.7505)
  line L8 (-43.9603, -31.7505) -> (-50.3603, -31.7505)
  line L9 (80.2, -31.7505) -> (73.8, -31.7505)
  line L10 (50.3603, -31.7505) -> (43.9603, -31.7505)
  line L11 (27.2022, -31.7505) -> (25, -31.7505)
  line L12 (27.2022, -31.7505) -> (31.9266, -31.7505)
  line L13 (43.5123, -31.7505) -> (31.9266, -31.7505)
  line L14 (43.5123, -31.7505) -> (80.6, -31.7505)
  line L15 (79.6046, -31.7505) -> (80.7, -31.7505)
  line L16 (50.7384, -31.7505) -> (79.6046, -31.7505)
  line L17 (47.1308, -31.7505) -> (50.7384, -31.7505)
  line L18 (-47.1308, -31.7505) -> (47.1308, -31.7505)
  line L19 (-50.7384, -31.7505) -> (-47.1308, -31.7505)
  line L20 (-79.6046, -31.7505) -> (-50.7384, -31.7505)
  line L21 (-80.7, -31.7505) -> (-79.6046, -31.7505)
  line L22 (-43.5123, -31.7505) -> (-80.6, -31.7505)
  line L23 (-31.9266, -31.7505) -> (-43.5123, -31.7505)
  line L24 (-31.9266, -31.7505) -> (-27.2022, -31.7505)
  line L25 (-25, -31.7505) -> (-27.2022, -31.7505)
  line L26 (-22.8564, -31.7505) -> (-25, -31.7505)
  line L27 (-13.8564, -31.7505) -> (-22.8564, -31.7505)
  line L28 (13.8564, -31.7505) -> (-13.8564, -31.7505)
  line L29 (22.8564, -31.7505) -> (13.8564, -31.7505)
  line L30 (25, -31.7505) -> (22.8564, -31.7505)
  line L31 (-6, -26.75) -> (-22.3427, -26.75)
  line L32 (-6, -26.75) -> (-3, -26.75)
  line L33 (3, -26.75) -> (6, -26.75)
  line L34 (22.3427, -26.75) -> (6, -26.75)
  line L35 (3, -26.75) -> (19.3427, -26.75)
  line L36 (-3, -26.75) -> (3, -26.75)
  line L37 (-19.3427, -26.75) -> (-3, -26.75)
  line L38 (-49.2006, -26.75) -> (-50.7603, -26.75)
  line L39 (-50, -31.7505) -> (-50, -26.75)
  line L40 (-44.592, -34.75) -> (-44.592, -26.75)
  line L41 (82.6, -34.75) -> (-82.6, -34.75)
  line L42 (44.592, -26.75) -> (44.592, -34.75)
  line L43 (61.7512, -26.75) -> (44.592, -26.75)
  curve K1 (78.3852, -26.75) -> (61.7512, -26.75)
  line L44 (82.6, -26.75) -> (16.6339, -26.75)
  curve K2 (-16.6339, -26.75) -> (16.6339, -26.75)
  line L45 (-16.6339, -26.75) -> (-82.6, -26.75)
  curve K3 (-61.7512, -26.75) -> (-78.3852, -26.75)
  line L46 (-44.592, -26.75) -> (-61.7512, -26.75)
  line L47 (21.6078, -26.75) -> (-21.6078, -26.75)
  line L48 (-21.6078, -26.75) -> (21.6078, -26.75)
  line L49 (-12.1244, -26.75) -> (-3, -26.75)
  line L50 (-21.1244, -26.75) -> (-12.1244, -26.75)
  line L51 (-23, -26.75) -> (-21.1244, -26.75)
  line L52 (21.1244, -26.75) -> (23, -26.75)
  line L53 (12.1244, -26.75) -> (21.1244, -26.75)
  line L54 (3, -26.75) -> (12.1244, -26.75)
  line L55 (-19.3427, -26.75) -> (-9, -26.75)
  line L56 (9, -26.75) -> (-9, -26.75)
  line L57 (9, -26.75) -> (19.3427, -26.75)
  line L58 (-32.8548, -26.75) -> (-32.3628, -26.75)
  line L59 (-29.266, -26.75) -> (-32.3628, -26.75)
  line L60 (-29.266, -26.75) -> (-28.774, -26.75)
  line L61 (-27.2256, -26.75) -> (-28.774, -26.75)
  line L62 (-27.2256, -26.75) -> (-27.2144, -26.75)
  line L63 (-28.774, -26.75) -> (-27.2256, -26.75)
  line L64 (-29.266, -26.75) -> (-28.774, -26.75)
  line L65 (-32.3628, -26.75) -> (-29.266, -26.75)
  line L66 (-32.8548, -26.75) -> (-32.3628, -26.75)
  line L67 (-34.4032, -26.75) -> (-32.8548, -26.75)
  line L68 (-34.4144, -26.75) -> (-34.4032, -26.75)
  line L69 (-32.8548, -26.75) -> (-34.4032, -26.75)
  line L70 (-75.4516, -26.75) -> (-74.9596, -26.75)
  line L71 (-78.5484, -26.75) -> (-75.4516, -26.75)
  line L72 (-79.0404, -26.75) -> (-78.5484, -26.75)
  line L73 (-80.5888, -26.75) -> (-79.0404, -26.75)
  line L74 (-80.6, -26.75) -> (-80.5888, -26.75)
  line L75 (-79.0404, -26.75) -> (-80.5888, -26.75)
  line L76 (-79.0404, -26.75) -> (-78.5484, -26.75)
  line L77 (-75.4516, -26.75) -> (-78.5484, -26.75)
  line L78 (-75.4516, -26.75) -> (-74.9596, -26.75)
  line L79 (-73.4112, -26.75) -> (-74.9596, -26.75)
  line L80 (-73.4112, -26.75) -> (-73.4, -26.75)
  line L81 (-74.9596, -26.75) -> (-73.4112, -26.75)
  line L82 (-30.35, -26.75) -> (-27.65, -26.75)
  line L83 (48.7086, -26.75) -> (49.2006, -26.75)
  line L84 (50.749, -26.75) -> (49.2006, -26.75)
  line L85 (50.749, -26.75) -> (50.7603, -26.75)
  line L86 (49.2006, -26.75) -> (50.749, -26.75)
  line L87 (48.7086, -26.75) -> (49.2006, -26.75)
  line L88 (45.6119, -26.75) -> (48.7086, -26.75)
  line L89 (45.1199, -26.75) -> (45.6119, -26.75)
  line L90 (43.5715, -26.75) -> (45.1199, -26.75)
  line L91 (43.5603, -26.75) -> (43.5715, -26.75)
  line L92 (45.1199, -26.75) -> (43.5715, -26.75)
  line L93 (45.1199, -26.75) -> (45.6119, -26.75)
  line L94 (48.7086, -26.75) -> (45.6119, -26.75)
  line L95 (27.65, -26.75) -> (30.35, -26.75)
  line L96 (28.774, -26.75) -> (29.266, -26.75)
  line L97 (32.3628, -26.75) -> (29.266, -26.75)
  line L98 (32.3628, -26.75) -> (32.8548, -26.75)
  line L99 (34.4032, -26.75) -> (32.8548, -26.75)
  line L100 (34.4032, -26.75) -> (34.4144, -26.75)
  line L101 (32.8548, -26.75) -> (34.4032, -26.75)
  line L102 (32.3628, -26.75) -> (32.8548, -26.75)
  line L103 (29.266, -26.75) -> (32.3628, -26.75)
  line L104 (28.774, -26.75) -> (29.266, -26.75)
  line L105 (27.2256, -26.75) -> (28.774, -26.75)
  line L106 (27.2144, -26.75) -> (27.2256, -26.75)
  line L107 (28.774, -26.75) -> (27.2256, -26.75)
  line L108 (78.5484, -26.75) -> (79.0404, -26.75)
  line L109 (75.4516, -26.75) -> (78.5484, -26.75)
  line L110 (74.9596, -26.75) -> (75.4516, -26.75)
  line L111 (73.4112, -26.75) -> (74.9596, -26.75)
  line L112 (73.4, -26.75) -> (73.4112, -26.75)
  line L113 (74.9596, -26.75) -> (73.4112, -26.75)
  line L114 (74.9596, -26.75) -> (75.4516, -26.75)
  line L115 (78.5484, -26.75) -> (75.4516, -26.75)
  line L116 (78.5484, -26.75) -> (79.0404, -26.75)
  line L117 (80.5888, -26.75) -> (79.0404, -26.75)
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  point P48 (-50, -31.7505)
  point P51 (-50, -26.75)
  point P52 (-50, -29.2502)
  coincident L22 P48
  coincident L38 P51
  perpendicular L8 L39
  midpoint L39 P52
  dimension "d273" diameter = 7
extrude "Extrude58" cut sketch "Sketch31" distance 20
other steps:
derived_base_feature "Derived Base Feature1"
derived_base_feature "Derived Base Feature1"
base_feature "Base Feature"
create_component "CreateComponent1"
create_component "CreateComponent2"
cylinder_primitive "CylinderPrimitive1" Height -7 Diameter 173
cylinder_primitive "CylinderPrimitive1" Height -7 Diameter 173

design "Solenoid JF-0826B"
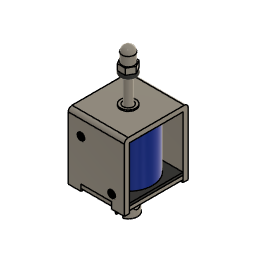
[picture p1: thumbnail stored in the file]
description: STEP AP214
part number: Solenoid JF-0826B

design "18650 battery variations" references "Battery 18650"
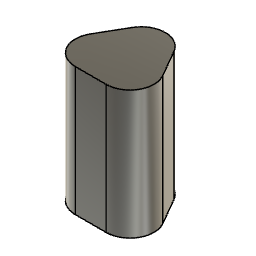
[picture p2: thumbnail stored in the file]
sketch "Sketch1" plane through (0, 0, 0) normal (0, 0, 1) x axis (1, 0, 0)
  line L1 (-16.7942, -0.6962) -> (-7.7942, 14.8923)
  line L2 (9, -14.1962) -> (-9, -14.1962)
  line L3 (7.7942, 14.8923) -> (16.7942, -0.6962)
  circle C1 centre (-9, -5.1962) radius 9
  circle C2 centre (9, -5.1962) radius 9
  circle C3 centre (0, 10.3923) radius 9
  point P4 (-16.7942, -0.6962)
  coincident C1 P4
  tangent C1 L1
  dimension "d6" diameter C1 = 18
  dimension "d11" C-Pattern1-Angle = 360
extrude "Extrude1" new body sketch "Sketch1" along normal blind 65
copy_paste_bodies "CopyPasteBodies2"
offset_faces "OffsetFaces1" distance 5
component_insert "Component Insert"
position "Position4"
step "00000000-0000-0000-0000-000000000000" TotalAngle 360
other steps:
base_feature "Base Feature"

design "25d-metal-gearmotor-20.4"
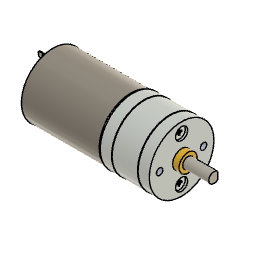
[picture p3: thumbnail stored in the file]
description: STEP AP214
part number: 25d-metal-gearmotor-20.4

design "25d-metal-gearmotor-34-47"
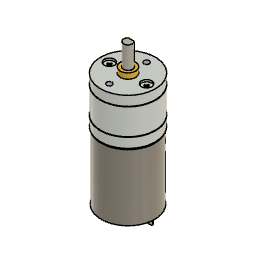
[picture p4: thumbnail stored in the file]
description: STEP AP214
part number: 25d-metal-gearmotor-34-47

design "light sensor"
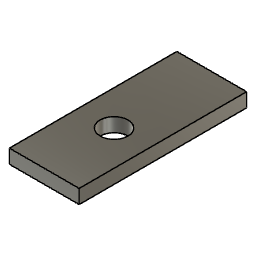
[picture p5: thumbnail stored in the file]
sketch "Sketch1" plane through (0, 0, 0) normal (0, 0, 1) x axis (1, 0, 0)
  line L1 (2.5, -6) -> (2.5, 6)
  line L2 (-2.5, -6) -> (2.5, -6)
  line L3 (-2.5, 6) -> (-2.5, -6)
  line L4 (2.5, 6) -> (-2.5, 6)
  circle C1 centre (0, -1) radius 1
  perpendicular L1 L2
  perpendicular L1 L4
canvas "Canvas1" sketch "Sketch1"
extrude "Extrude1" new body sketch "Sketch1" against normal blind 1

design "cam v2.1 rpi"
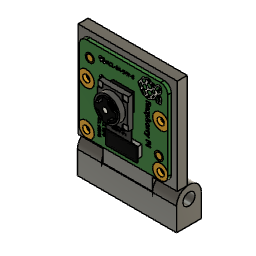
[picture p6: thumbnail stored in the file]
base_feature "Base Feature2"
position "Position1"
base_feature "Base Feature1"
position "Position2"
position "Position3"
position "Position4"
position "Position5"
position "Position6"
position "Position7"
position "Position8"
copy_paste_bodies "CutPasteBodies"
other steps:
base_feature "Base Feature1" bodies "camera mount", "2nd floor"
create_component "CreateComponent1"
named bodies: "camera mount", "2nd floor"

design "omniwheel"
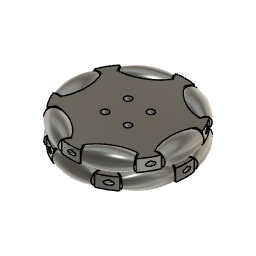
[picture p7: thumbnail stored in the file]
sketch "Sketch1" plane through (0, 0, 0) normal (0, 0, 1) x axis (1, 0, 0)
  line L1 (20.3961, 22) -> (-20.3961, 22)
  line L2 (0, 14) -> (0, 30)
  line L3 (15, 18.0192) -> (15, 25.9808)
  line L4 (-15, 18.0192) -> (-15, 25.9808)
  line L5 (-8.1051, -22) -> (-15, -25.9808)
  line L6 (-29.2506, 6.6635) -> (-8.8545, -28.6635)
  line L7 (-12.1244, -7) -> (-25.9808, -15)
  line L8 (-23.1051, 3.9808) -> (-30, 0)
  line L9 (23.1051, 3.9808) -> (30, 0)
  line L10 (8.8545, -28.6635) -> (29.2506, 6.6635)
  line L11 (12.1244, -7) -> (25.9808, -15)
  line L12 (8.1051, -22) -> (15, -25.9808)
  circle C1 centre (0, 0) radius 30
  arc A1 centre (0, 44) radius 30 clockwise from (20.3961, 22) to (-20.3961, 22)
  arc A2 centre (-38.1051, -22) radius 30 clockwise from (-29.2506, 6.6635) to (-8.8545, -28.6635)
  arc A3 centre (38.1051, -22) radius 30 clockwise from (8.8545, -28.6635) to (29.2506, 6.6635)
  point P1 (0, 0)
  point P2 (0, 0)
  point P6 (0, 30)
  point P7 (0, 14)
  point P8 (15, 25.9808)
  point P9 (15, 18.0192)
  coincident P1 P2
  horizontal L1
  coincident C1 P6
  midpoint A1 P7
  vertical L2
  coincident C1 P8
  coincident A1 P9
  perpendicular L1 L3
  dimension "d8" C-Pattern1-Angle = 360
extrude "Extrude1" new body sketch "Sketch1" distance 3 bodies "koliesko1"
revolve "Revolve1" sketch "Sketch1" AlongAngle 360
circular_pattern "C-Pattern1" TotalAngle 360
sketch "Sketch2" plane through (-7.5, 12.9904, 0) normal (0.5, -0.866, 0) x axis (0.866, 0.5, 0)
  line L1 (-25.9808, -3) -> (-25.9808, 3)
  line L2 (-19.3834, -3) -> (-25.9808, -3)
  line L3 (-25.9808, 3) -> (-19.3834, 3)
  arc A1 centre (-22, 0) radius 3.9808 clockwise from (-19.3834, 3) to (-19.3834, -3)
  circle C1 centre (-22, 0) radius 1.5
  circle C2 centre (-22, 0) radius 3.9808
  concentric A1 C1
  concentric C1 C2
revolve "Revolve2" sketch "Sketch1" AlongAngle 360 bodies "valcek"
extrude "Extrude2" cut sketch "Sketch2" profile of C1 against normal blind 2.5 and along normal blind 32.5
offset_faces "OffsetFaces6" distance -0.2
circular_pattern "C-Pattern2" TotalAngle 360
offset_faces "OffsetFaces1" distance -0.2
circular_pattern "C-Pattern3" TotalAngle 360
sketch "Sketch3" plane through (0, 0, 3) normal (0, 0, 1) x axis (-1, 0, 0)
  line L1 (14.7991, 26.0957) -> (9.0374, 22.7692)
  line L2 (-9.0374, 22.7692) -> (-14.7991, 26.0957)
  curve K1 (-24.2374, -3.558) -> (-9.0374, 22.7692)
  line L3 (-29.9991, -0.2315) -> (-24.2374, -3.558)
  line L4 (-15.2, -19.2113) -> (-15.2, -25.8643)
  curve K2 (15.2, -19.2113) -> (-15.2, -19.2113)
  line L5 (15.2, -25.8643) -> (15.2, -19.2113)
  line L6 (24.2374, -3.558) -> (29.9991, -0.2315)
  curve K3 (9.0374, 22.7692) -> (24.2374, -3.558)
  curve K4 (-15.2, 19.2113) -> (15.2, 19.2113)
  line L7 (-15.2, 25.8643) -> (-15.2, 19.2113)
  line L8 (-24.2374, 3.558) -> (-29.9991, 0.2315)
  curve K5 (-9.0374, -22.7692) -> (-24.2374, 3.558)
  line L9 (-14.7991, -26.0957) -> (-9.0374, -22.7692)
  line L10 (9.0374, -22.7692) -> (14.7991, -26.0957)
  curve K6 (24.2374, 3.558) -> (9.0374, -22.7692)
  line L11 (29.9991, 0.2315) -> (24.2374, 3.558)
  line L12 (15.2, 19.2113) -> (15.2, 25.8643)
  arc A1 centre (0, 0) radius 30 clockwise from (-14.7991, 26.0957) to (14.7991, 26.0957)
  arc A2 centre (0, 0) radius 30 clockwise from (-15.2, -25.8643) to (-29.9991, -0.2315)
  arc A3 centre (0, 0) radius 30 clockwise from (29.9991, -0.2315) to (15.2, -25.8643)
  circle C1 centre (0, 0) radius 14.3685
  circle C2 centre (5.5, -5.5) radius 1.5
  circle C3 centre (-5.5, -5.5) radius 1.5
  circle C4 centre (5.5, 5.5) radius 1.5
  circle C5 centre (-5.5, 5.5) radius 1.5
  arc A4 centre (0, 0) radius 30 clockwise from (-29.9991, 0.2315) to (-15.2, 25.8643)
  arc A5 centre (0, 0) radius 30 clockwise from (14.7991, -26.0957) to (-14.7991, -26.0957)
  arc A6 centre (0, 0) radius 30 clockwise from (15.2, 25.8643) to (29.9991, 0.2315)
  dimension "d26" R-Pattern1-uDistance = -11
  dimension "d27" R-Pattern1-vDistance = 11
extrude "Extrude3" new body sketch "Sketch3" profile of C1 C2 C3 C4 C5 along normal blind 6 bodies "spacer"
extrude "Extrude7" cut sketch "Sketch3" profile of C2 C3 C4 C5 along normal blind 6 and against normal blind 6
offset_faces "OffsetFaces5" distance -0.2
offset_faces "OffsetFaces7" distance -0.35
split "Split2" bodies "koliesko2 (ten isty tvar)"
copy_paste_bodies "CopyPasteBodies3"
move "Move3"
sketch "Sketch4" plane through (0, 0, 0) normal (0, 0, 1) x axis (1, 0, 0)
  line L1 (30, 0) -> (0, 0)
  line L2 (-7.7646, 28.9778) -> (7.7646, 28.9778)
  line L3 (0, 30) -> (0, 0)
  line L4 (15, 25.9808) -> (0, 0)
  line L5 (-15, 25.9808) -> (0, 0)
  line L6 (-30, 0) -> (0, 0)
  line L7 (-15, -25.9808) -> (0, 0)
  line L8 (15, -25.9808) -> (0, 0)
  line L9 (9.7646, 28.3664) -> (-9.7646, 28.3664)
  line L10 (-19.6837, 22.6396) -> (-29.4483, 5.7268)
  line L11 (-29.4483, -5.7268) -> (-19.6837, -22.6396)
  line L12 (-9.7646, -28.3664) -> (9.7646, -28.3664)
  line L13 (19.6837, -22.6396) -> (29.4483, -5.7268)
  line L14 (29.4483, 5.7268) -> (19.6837, 22.6396)
  line L15 (-9.7646, 28.3664) -> (-9.7646, 22.3664)
  line L16 (9.7646, 28.3664) -> (9.7646, 22.3664)
  line L17 (9.7646, 25.3664) -> (-9.7646, 25.3664)
  line L18 (9.7646, 25.8664) -> (9.7646, 25.3664)
  line L19 (-9.7646, 26.1164) -> (9.7646, 26.1164)
  circle C1 centre (0, 0) radius 30
  arc A1 centre (0, 50.7328) radius 30 clockwise from (9.7646, 22.3664) to (-9.7646, 22.3664)
  circle C2 centre (5.75, -5.75) radius 1.5
  circle C3 centre (-5.75, -5.75) radius 1.5
  circle C4 centre (5.75, 5.75) radius 1.5
  circle C5 centre (-5.75, 5.75) radius 1.5
  circle C6 centre (0, 0) radius 11
  circle C7 centre (0, 0) radius 5
  circle C8 centre (0, 0) radius 20.7328
  point P1 (0, 0)
  point P2 (0, 0)
  point P3 (0, 0)
  point P4 (30, 0)
  point P7 (0, 0)
  point P8 (0, 30)
  point P19 (-9.7646, 28.3664)
  point P20 (9.7646, 28.3664)
  point P34 (-9.7646, 25.3664)
  point P35 (9.7646, 25.3664)
  point P17 (0, 0)
  point P41 (0, 0)
  point P13 (0, 0)
  point P43 (0, 0)
  coincident P1 P2
  coincident P2 P3
  coincident C1 P4
  horizontal L1
  coincident P1 P7
  coincident C1 P8
  perpendicular L2 L3
  coincident C1 P19
  coincident C1 P20
  perpendicular L9 L15
  perpendicular L9 L16
  midpoint L15 P34
  midpoint L16 P35
  perpendicular L9 L18
  coincident P17 P41
  concentric C1 C7
  coincident P13 P43
  tangent A1 C8
  dimension "d58" C-Pattern1-Angle = 360
  dimension "d61" C-Pattern2-Angle = 360
  dimension "d84" R-Pattern1-uDistance = -11.5
  dimension "d85" R-Pattern1-vDistance = 11.5
revolve "Revolve3" sketch "Sketch4" AlongAngle 360 bodies "valcek (1)"
extrude "Extrude8" new body sketch "Sketch4" profile of C1 L3 L4 L5 A1 L15 L16 L17 L18 distance 3 bodies "body hole"
combine "Combine1"
sketch "Sketch6" plane through (0, 0, 0) normal (1, 0, 0) x axis (0, 1, 0)
  line L1 (25.3664, -3) -> (25.3664, 0)
  line L2 (25.3664, 3) -> (25.3664, 0)
  line L3 (0, -3) -> (25.3664, -3)
  line L4 (0, 3) -> (0, -3)
  line L5 (25.3664, 3) -> (0, 3)
  line L6 (25.3664, 0) -> (25.8967, 0.5303)
  line L7 (25.3664, 1.0607) -> (25.8967, 0.5303)
  line L8 (24.8361, 0.5303) -> (25.3664, 1.0607)
  line L9 (30, 3) -> (0, 3)
  line L10 (30, -3) -> (30, 3)
  line L11 (25.3664, -3) -> (30, -3)
  circle C1 centre (25.3664, 0) radius 3
  circle C2 centre (25.3664, 0) radius 0.75
  point P2 (25.3664, 0)
  point P3 (25.3664, 0)
  point P4 (25.3664, -3)
  point P5 (25.3664, 3)
  point P9 (25.8967, 0.5303)
  point P8 (25.3664, 0)
  point P10 (25.3664, 0)
  point P11 (25.3664, 1.0607)
  point P12 (24.8361, 0.5303)
  coincident P2 P3
  coincident C1 P4
  vertical L1
  coincident C1 P5
  parallel L1 L2
  perpendicular L1 L3
  perpendicular L3 L4
  perpendicular L2 L5
  coincident C2 P9
  coincident P8 P10
  coincident L2 P11
  tangent C2 L7
  coincident C2 P12
  tangent C2 L8
  perpendicular L4 L9
  perpendicular L3 L10
  perpendicular L1 L11
offset_faces "OffsetFaces8" distance -0.5
revolve "Revolve6" AlongAngle 300
extrude "Extrude9" cut sketch "Sketch6" profile of L1 L2 C2 L6 L7 L8 along normal blind 19 and against normal blind 11.265
revolve "Revolve5" sketch "Sketch6" AlongAngle 35 AgainstAngle 35
combine "Combine2"
offset_faces "OffsetFaces9" distance -1
offset_faces "OffsetFaces12" distance -0.3
circular_pattern "C-Pattern5" TotalAngle 360
combine "Combine3"
offset_faces "OffsetFaces11" distance -0.2
extrude "Extrude10" cut sketch "Sketch4" profile of C2 C3 C4 C5 distance 3
copy_paste_bodies "CopyPasteBodies5"
move "Move5"
extrude "Extrude11" cut sketch "Sketch4" profile of L1 L3 L4 L5 L6 L7 L8 C7 against normal blind 3
extrude "Extrude12" cut sketch "Sketch4" profile of L1 L3 L4 L5 L6 L7 L8 C2 C3 C4 C5 C6 C7 along normal blind 3
extrude "Extrude13" new body sketch "Sketch4" profile of L1 L3 L4 L5 L6 L7 L8 C2 C3 C4 C5 C6 C7 C8 along normal blind 5 and along normal blind 3 bodies "spacer (1)"
offset_faces "OffsetFaces10" distance -0.2
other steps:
base_feature "Base Feature3"
base_feature "Base Feature5" bodies "body"
named bodies: "koliesko1", "valcek", "spacer", "koliesko2 (ten isty tvar)", "valcek (1)", "body hole", "body", "spacer (1)"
